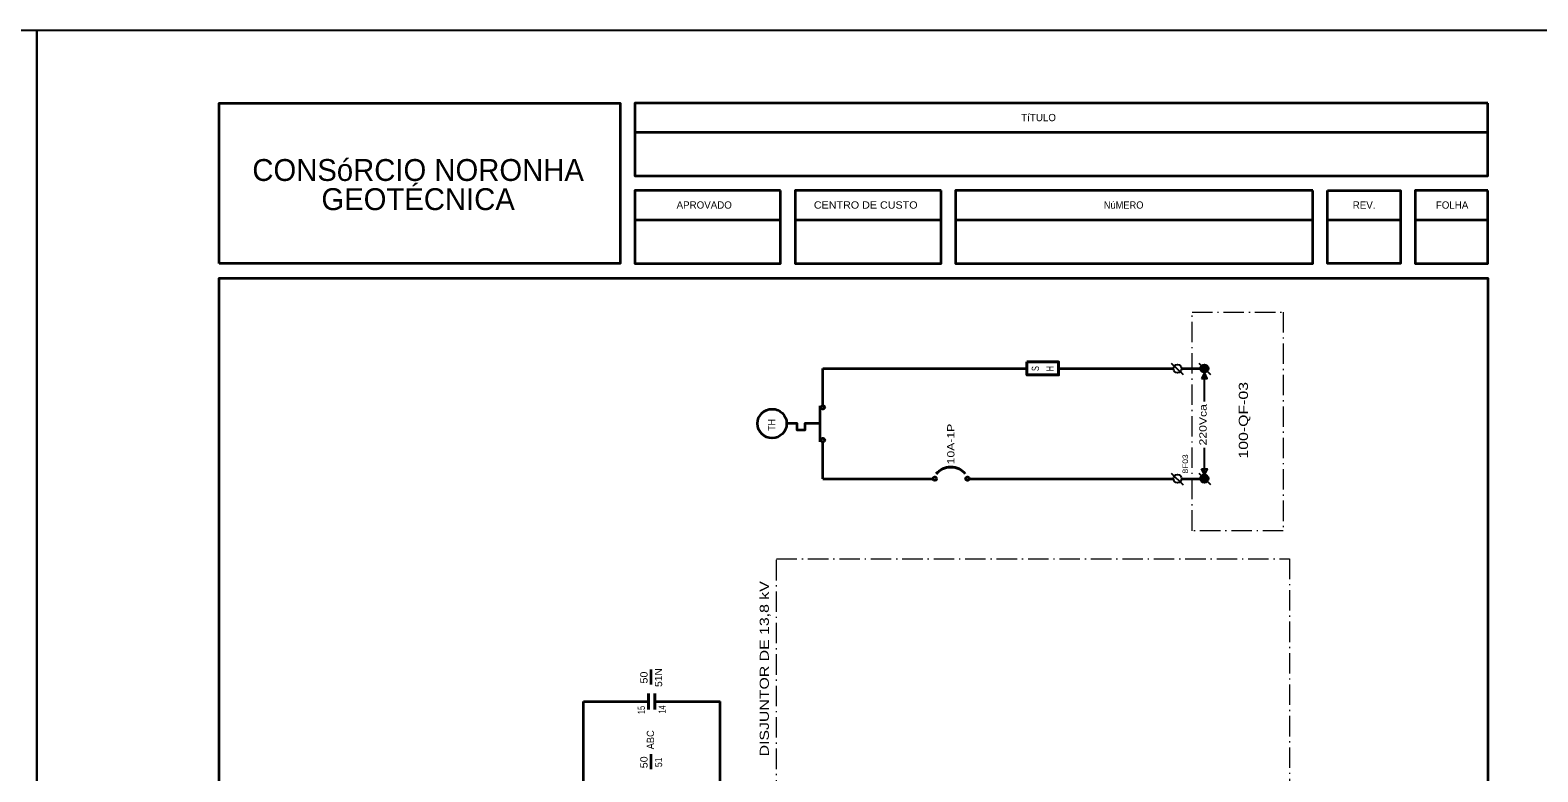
# Model space of a CAD drawing. Extents: x -4160 to -2690, y -474 to 714.
# Drawn here: x -3950.7 to -3743.9, y 18.7 to 120.5 of the extents above; entities that cross this region are included whole.
import ezdxf
from ezdxf.enums import TextEntityAlignment as Align

# ---------------------------------------------------------------- set-up
doc = ezdxf.new("R2010")
doc.units = 0
doc.header["$LTSCALE"] = 0.56
doc.linetypes.add('DOT_DASHED', pattern=[7.7, 5, -1.2, 0.3, -1.2])
doc.layers.add('1', color=7, linetype='Continuous', lineweight=25)
doc.layers.add('5', color=7, linetype='Continuous', lineweight=35)

msp = doc.modelspace()

# ---------------------------------------------------------------- hatches: boundary and pattern name
at = {"layer": '1'}
for points in [[(-3789.6467, 74.6268, 1), (-3789.6467, 73.503, 1)], [(-3789.6467, 59.5277, 1), (-3789.6467, 58.4038, 1)]]:
    msp.add_hatch(color=256, dxfattribs=at).paths.add_polyline_path(points)

# ---------------------------------------------------------------- linework, layer by layer
for p, q in [((-3792.5166, 73.1855), (-3794.1396, 74.7591)), ((-3788.7512, 73.1953), (-3790.3742, 74.7689)), ((-3789.6467, 69.5227), (-3789.6467, 73.5029)), ((-3789.6467, 59.5277), (-3789.6468, 63.1635)), ((-3792.5166, 58.0863), (-3794.1396, 59.6599)), ((-3788.7512, 58.0961), (-3790.3742, 59.6697))]:
    msp.add_line(p, q, dxfattribs=at)
at = {"layer": '1', "lineweight": 35}
for p, q in [((-3841.9694, 74.0741), (-3813.9868, 74.0741)), ((-3841.9694, 68.9927), (-3841.9694, 74.0741)), ((-3809.6326, 74.074), (-3793.9036, 74.074)), ((-3792.7804, 74.074), (-3790.2086, 74.074)), ((-3842.3442, 64.0215), (-3842.3442, 68.9513)), ((-3841.9694, 58.9493), (-3841.9694, 63.9927)), ((-3841.9694, 58.9493), (-3826.8728, 58.9493)), ((-3821.8966, 58.9493), (-3793.9039, 58.9493)), ((-3792.7802, 58.9493), (-3790.2084, 58.9493)), ((-3865.5063, 30.7185), (-3865.5063, 32.7861)), ((-3874.7921, 28.3953), (-3865.9007, 28.3953)), ((-3874.7921, -16.04), (-3874.7921, 28.3953)), ((-3864.9927, 28.3953), (-3856.0327, 28.3953)), ((-3856.0327, 6.1671), (-3856.0327, 28.3953)), ((-3865.5063, 19.0947), (-3865.5063, 21.1623))]:
    msp.add_line(p, q, dxfattribs=at)
at = {"layer": '1', "lineweight": 40}
for p, q in [((-3865.9007, 27.3019), (-3865.9007, 29.4885)), ((-3864.9927, 27.3019), (-3864.9927, 29.4885))]:
    msp.add_line(p, q, dxfattribs=at)
at = {"layer": '1', "linetype": 'DOT_DASHED', "lineweight": 13}
for points in [[(-3791.3339, 51.8125), (-3791.3339, 81.8125), (-3778.8339, 81.8125), (-3778.8339, 51.8125)], [(-3848.3279, -136.1027), (-3848.3279, 47.9667), (-3777.9927, 47.9667), (-3777.9927, -136.1027)]]:
    msp.add_lwpolyline(points, close=True, dxfattribs=at)
at = {"layer": '1', "lineweight": 40}
msp.add_lwpolyline([(-3813.9868, 74.9599), (-3809.6326, 74.9599), (-3809.6326, 73.1882), (-3813.9868, 73.1882)], close=True, dxfattribs=at)
at = {"layer": '1'}
for points in [[(-3790.0246, 72.7075), (-3789.2687, 72.7075), (-3789.6467, 73.5029)], [(-3790.0246, 60.3232), (-3789.2688, 60.3232), (-3789.6467, 59.5277)]]:
    msp.add_lwpolyline(points, close=True, dxfattribs=at)
at = {"layer": '1', "lineweight": 35}
msp.add_lwpolyline([(-3842.3442, 66.5117), (-3844.442, 66.5117), (-3844.442, 65.6015), (-3845.5054, 65.6015), (-3845.5054, 66.5117), (-3846.9341, 66.5117)], dxfattribs=at)
at = {"layer": '1'}
for centre in [(-3793.342, 74.0551), (-3789.6467, 74.0649), (-3793.342, 58.956), (-3789.6467, 58.9657)]:
    msp.add_circle(centre, 0.5619, dxfattribs=at)
at = {"layer": '1', "lineweight": 35}
for centre, radius in [((-3848.9331, 66.5117), 1.999), ((-3841.9694, 68.7427), 0.25), ((-3841.9694, 64.2428), 0.25), ((-3826.6229, 58.9493), 0.25), ((-3822.1466, 58.9494), 0.25)]:
    msp.add_circle(centre, radius, dxfattribs=at)
at = {"layer": '1', "lineweight": 40}
msp.add_ellipse((-3824.426, 58.5025), major_axis=(-2.3822, 0), ratio=0.85, start_param=3.72133334, end_param=5.70344457, dxfattribs=at)
at = {"layer": '5'}
for p, q in [((-3867.7642, 106.48), (-3750.7642, 106.48)), ((-3867.7642, 94.48), (-3847.7642, 94.48)), ((-3845.7642, 94.48), (-3825.7642, 94.48)), ((-3823.7642, 94.48), (-3774.7642, 94.48)), ((-3772.7642, 94.48), (-3762.7642, 94.48)), ((-3760.7642, 94.48), (-3750.7642, 94.48))]:
    msp.add_line(p, q, dxfattribs=at)
at = {"layer": '5', "lineweight": 25}
msp.add_lwpolyline([(-4159.7642, 120.48), (-3949.7642, 120.48), (-3949.7642, -176.52)], dxfattribs=at)
msp.add_lwpolyline([(-3739.7642, -176.52), (-3949.7642, -176.52), (-3949.7642, 120.48), (-3739.7642, 120.48)], close=True, dxfattribs=at)
at = {"layer": '5'}
for points in [[(-3924.7642, 88.48), (-3924.7642, 110.48), (-3869.7642, 110.48), (-3869.7642, 88.48)], [(-3750.7642, 110.48), (-3867.7642, 110.48), (-3867.7642, 100.48), (-3750.7642, 100.48)], [(-3847.7642, 98.48), (-3867.7642, 98.48), (-3867.7642, 88.48), (-3847.7642, 88.48)], [(-3825.7642, 98.48), (-3845.7642, 98.48), (-3845.7642, 88.48), (-3825.7642, 88.48)], [(-3774.7642, 98.48), (-3823.7642, 98.48), (-3823.7642, 88.48), (-3774.7642, 88.48)], [(-3772.7642, 98.48), (-3762.7642, 98.48), (-3762.7642, 88.48), (-3772.7642, 88.48)], [(-3750.7642, 98.48), (-3760.7642, 98.48), (-3760.7642, 88.48), (-3750.7642, 88.48)], [(-3924.7642, -166.52), (-3924.7642, 86.48), (-3750.7642, 86.48), (-3750.7642, -166.52)]]:
    msp.add_lwpolyline(points, close=True, dxfattribs=at)

# ---------------------------------------------------------------- texts
at = {"layer": '1'}
for s, height, width, p in [('S', 1, 0.7, (-3812.3274, 74.0559)), ('H', 1, 0.6, (-3810.3274, 74.0559)), ('100-QF-03', 1.25, 1.3, (-3783.677, 66.9622)), ('220Vca', 1, 1.25, (-3789.3436, 66.3453)), ('TH', 1, 0.9, (-3848.5102, 66.3288)), ('10A-1P', 1, 1.25, (-3823.9235, 63.7047)), ('8F03', 0.75, 1.15, (-3791.895, 60.9752)), ('DISJUNTOR DE 13,8 kV', 1.25, 1.3, (-3849.378, 32.8745)), ('50', 1, 1.1, (-3866.0101, 31.6709)), ('51N', 1, 1.05, (-3864.0101, 31.6708)), ('15', 1, 0.6, (-3866.3619, 27.2249)), ('14', 1, 0.6, (-3863.5079, 27.2963)), ('ABC', 1, 0.95, (-3865.1183, 23.1338)), ('50', 1, 1.1, (-3866.0101, 20.0471)), ('51', 1, 0.9, (-3864.0101, 20.0471))]:
    msp.add_text(s, height=height, rotation=90, dxfattribs=dict(at, width=width)).set_placement(p, align=Align.CENTER)
at = {"layer": '5'}
for s, height, p in [('TíTULO', 1, (-3812.3847, 107.991)), ('CONSóRCIO NORONHA', 3, (-3897.4749, 99.7961)), ('GEOTÉCNICA', 3, (-3897.475, 95.7961)), ('APROVADO', 1, (-3858.2387, 95.9973)), ('REV.', 1, (-3767.7444, 95.9923)), ('FOLHA', 1, (-3755.681, 95.9923))]:
    msp.add_text(s, height=height, dxfattribs=at).set_placement(p, align=Align.CENTER)
for s, width, p in [('CENTRO DE CUSTO', 1.1, (-3836.0934, 95.9973)), ('NúMERO', 0.95, (-3800.7228, 95.9923))]:
    msp.add_text(s, height=1, dxfattribs=dict(at, width=width)).set_placement(p, align=Align.CENTER)

doc.saveas('drawing.dxf')
